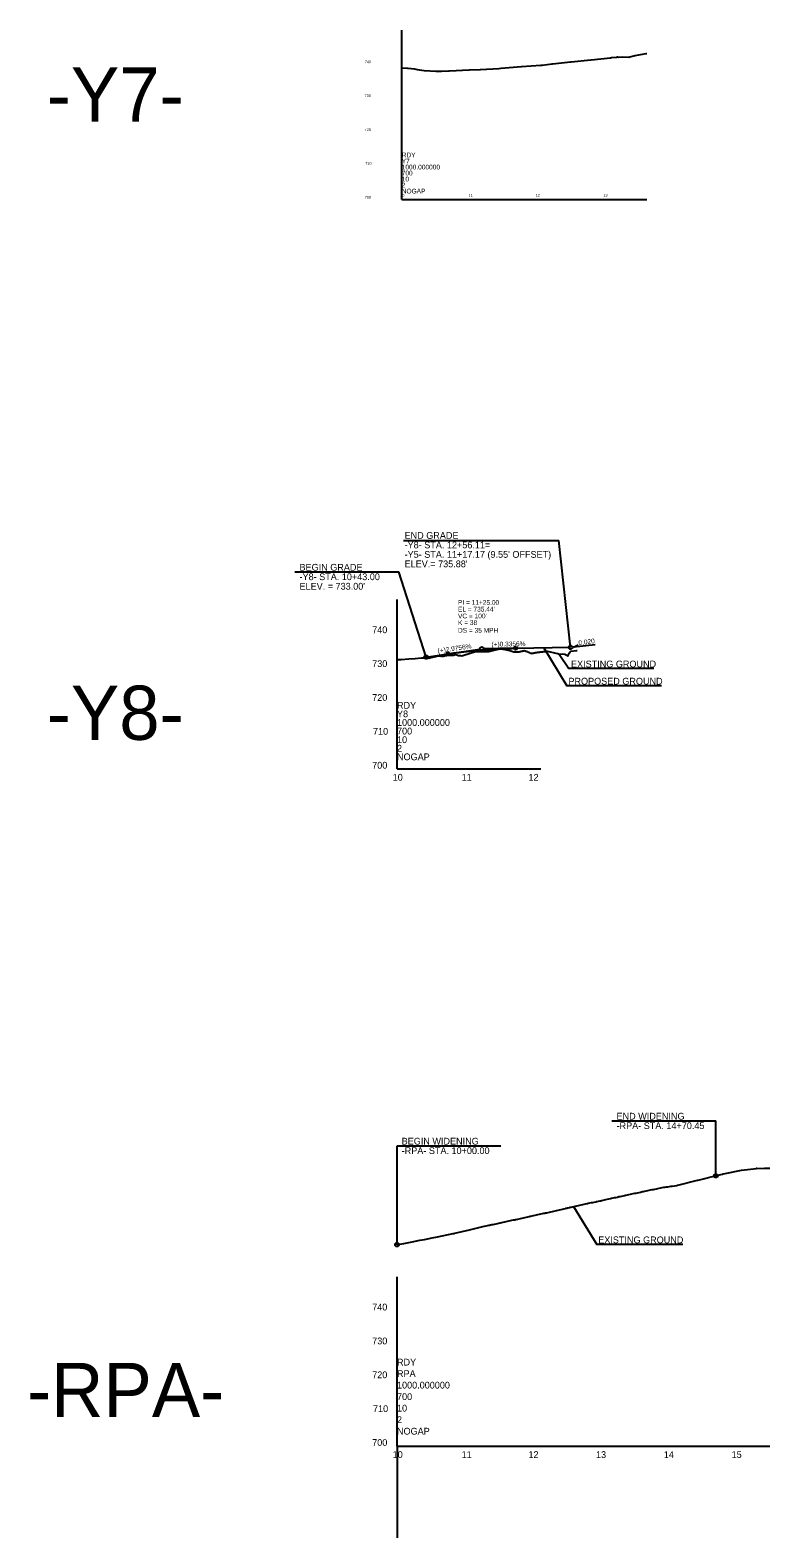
# Model space of a CAD drawing. Extents: x 1554255 to 1803987, y 659549 to 692876.
# Drawn here: x 1554255 to 1555346, y 683333 to 685559 of the extents above; entities that cross this region are included whole.
import ezdxf

# ---------------------------------------------------------------- set-up
doc = ezdxf.new("R2010")
doc.units = 0
for name, color, linetype in [('Default', 7, 'Continuous'), ('Exist Profile Cell', 7, 'Continuous'), ('Exist Vertical Profile Ground Line', 7, 'Continuous'), ('Exist Vertical Profile Horizontal Axis Label Major', 7, 'Continuous'), ('Exist Vertical Profile Vertical Axis Label', 7, 'Continuous'), ('Prop PFL Text', 7, 'Continuous'), ('Prop Vertical Profile Curve Label', 7, 'Continuous'), ('Prop Vertical Profile Grade', 7, 'Continuous'), ('Prop Vertical Profile Grade Label', 7, 'Continuous'), ('Prop VPI Label', 7, 'Continuous')]:
    doc.layers.add(name, color=color, linetype=linetype)

msp = doc.modelspace()

# ---------------------------------------------------------------- linework, layer by layer
at = {"layer": 'Exist Profile Cell'}
for p, q in [((1554802.9, 685309.3), (1554802.9, 685559.3)), ((1554802.9, 685309.3), (1555164.5, 685309.3)), ((1554802.9, 685309.3), (1554802.9, 685309.3)), ((1554795.9, 684468.6), (1554795.9, 684718.6)), ((1554795.9, 684468.6), (1555007.9, 684468.6)), ((1554795.9, 684468.6), (1554795.9, 684468.6)), ((1554795.9, 683468.6), (1554795.9, 683718.6)), ((1554795.9, 683468.6), (1555345.9, 683468.6)), ((1554795.9, 683468.6), (1554795.9, 683468.6))]:
    msp.add_line(p, q, dxfattribs=at)
at = {"layer": 'Exist Vertical Profile Ground Line'}
for points in [[(1554802.9, 685503.8), (1554811.3, 685503.2), (1554812.4, 685503.1), (1554821.5, 685502), (1554823.7, 685501.7), (1554825.5, 685501.4), (1554835.9, 685499.9), (1554853.4, 685498.8), (1554861.4, 685498.7), (1554872.6, 685499.3), (1554873.2, 685499.3), (1554902.2, 685500.7), (1554903, 685500.7), (1554918.5, 685501.4), (1554918.9, 685501.4), (1554946, 685502.8), (1554949.1, 685503), (1554949.8, 685503.1), (1554979, 685505.4), (1554979.8, 685505.4), (1555008.3, 685507.7), (1555010, 685507.8), (1555024.6, 685509.7), (1555025.3, 685509.7), (1555051.7, 685512.5), (1555052.6, 685512.6), (1555081.8, 685515.6), (1555082.2, 685515.6), (1555110.8, 685518.6), (1555112.5, 685518.8), (1555119.8, 685519.6), (1555121, 685519.7), (1555122.6, 685519.6), (1555128.3, 685519.7), (1555137.9, 685519.6), (1555139.3, 685519.9), (1555145.4, 685521.4), (1555146.9, 685521.8), (1555147.3, 685521.8), (1555163.7, 685524.8), (1555164.5, 685524.9)], [(1554795.9, 684630.1), (1554802, 684630.1), (1554813.5, 684631.1), (1554822.5, 684631.6), (1554832, 684632.5), (1554839.6, 684632.7), (1554840.3, 684632.5), (1554842.8, 684632.2), (1554844.5, 684632.5), (1554848.6, 684633.5), (1554857.8, 684635.2), (1554860.7, 684634.9), (1554861.3, 684635.3), (1554862.4, 684634.8), (1554864.6, 684634.9), (1554868.7, 684635.9), (1554870.1, 684636.2), (1554870.6, 684636.2), (1554879.1, 684636.2), (1554882.2, 684637.2), (1554882.9, 684637.2), (1554886.4, 684636.1), (1554889.4, 684636.1), (1554891.5, 684635.6), (1554905.2, 684639.7), (1554910.4, 684641.4), (1554911.1, 684641.6), (1554911.9, 684641.8), (1554912.6, 684641.8), (1554913.4, 684641.8), (1554914.1, 684641.8), (1554914.9, 684641.8), (1554915.6, 684641.8), (1554916.4, 684641.8), (1554917.1, 684641.8), (1554917.9, 684641.8), (1554918.6, 684641.8), (1554919.4, 684641.8), (1554920.1, 684641.9), (1554920.9, 684641.9), (1554921.6, 684641.9), (1554922.4, 684641.9), (1554923.1, 684641.9), (1554923.8, 684641.9), (1554924.6, 684641.9), (1554925.3, 684641.9), (1554926.1, 684641.9), (1554926.8, 684641.9), (1554927.6, 684641.8), (1554928.3, 684641.8), (1554929.1, 684641.8), (1554929.8, 684641.8), (1554930.6, 684641.8), (1554931, 684641.8), (1554931.3, 684641.9), (1554932.1, 684642.1), (1554932.8, 684642.3), (1554933.6, 684642.5), (1554934.3, 684642.7), (1554935.1, 684642.9), (1554935.8, 684643.1), (1554936.6, 684643.3), (1554937.3, 684643.5), (1554938.1, 684643.7), (1554938.8, 684643.9), (1554939.6, 684644.1), (1554940.3, 684644.3), (1554941.2, 684644.5), (1554941.8, 684644.7), (1554942.6, 684644.8), (1554943.3, 684645), (1554944, 684645.2), (1554944.8, 684645.3), (1554945.5, 684645.5), (1554946.3, 684645.7), (1554947, 684645.8), (1554947.8, 684646), (1554948.6, 684646.2), (1554949.3, 684646), (1554950, 684645.9), (1554950.8, 684645.8), (1554951.5, 684645.6), (1554952.3, 684645.5), (1554953, 684645.4), (1554953.8, 684645.2), (1554954.5, 684645.1), (1554955.3, 684644.9), (1554956, 684644.8), (1554956.8, 684644.7), (1554957.5, 684644.5), (1554958.3, 684644.4), (1554959, 684644.2), (1554959.8, 684644), (1554960.5, 684643.9), (1554960.9, 684643.8), (1554961.3, 684643.7), (1554962, 684643.5), (1554962.7, 684643.2), (1554963.5, 684643), (1554964.2, 684642.7), (1554965, 684642.5)], [(1554965, 684642.5), (1554965.7, 684642.2), (1554966.5, 684642), (1554967.2, 684641.7), (1554968, 684641.5), (1554968.7, 684641.2), (1554969.5, 684641.2), (1554970.2, 684641.2), (1554971, 684641.2), (1554971.7, 684641.2), (1554972.5, 684641.2), (1554973.2, 684641.1), (1554974, 684641.1), (1554974.3, 684641.1), (1554974.7, 684641.2), (1554975.5, 684641.4), (1554976.2, 684641.5), (1554977, 684641.7), (1554977.7, 684641.9), (1554978.5, 684642), (1554979.2, 684642.2), (1554980, 684642.4), (1554980.7, 684642.5), (1554981.5, 684642.7), (1554982.2, 684642.8), (1554982.9, 684642.9), (1554983.7, 684643.1), (1554984, 684643.1), (1554984.4, 684643), (1554985.2, 684642.7), (1554985.9, 684642.4), (1554986.7, 684642.1), (1554987.4, 684641.9), (1554988.2, 684641.6), (1554988.9, 684641.3), (1554989.7, 684641), (1554990.4, 684640.7), (1554991.2, 684640.4), (1554991.9, 684640.1), (1554992.7, 684639.7), (1554993.4, 684639.4), (1554994.3, 684639), (1554994.9, 684639.2), (1554995.7, 684639.3), (1554996.4, 684639.5), (1554997.2, 684639.6), (1554997.9, 684639.8), (1554998.7, 684639.9), (1554999.4, 684640), (1555000.2, 684640.2), (1555000.9, 684640.3), (1555001.9, 684640.5), (1555002.4, 684640.6), (1555003.1, 684640.7), (1555003.9, 684640.7), (1555004.6, 684640.8), (1555005.4, 684640.9), (1555006.1, 684641), (1555006.9, 684641.1), (1555007.6, 684641.2), (1555008.4, 684641.3), (1555009.1, 684641.3), (1555009.9, 684641.4), (1555010.6, 684641.5), (1555011.4, 684641.6), (1555012.1, 684641.7), (1555012.9, 684641.8), (1555013.6, 684641.8), (1555014.4, 684641.9), (1555015.1, 684642), (1555017.9, 684642.3), (1555030.1, 684639.5), (1555033.1, 684638.7), (1555035.1, 684638.1), (1555040.3, 684638.5), (1555043.3, 684637.9), (1555046.3, 684636.6), (1555047.7, 684634.9), (1555050.6, 684639.9), (1555051.5, 684641.1), (1555052, 684642), (1555052.5, 684642.2), (1555060.7, 684643.1), (1555061.2, 684643.2), (1555061.6, 684643.2)], [(1554795.9, 683766), (1554797.3, 683766.2), (1554800.3, 683766.8), (1554805.8, 683767.6), (1554818.3, 683770.1), (1554829.5, 683772.5), (1554836.3, 683773.6), (1554847.7, 683776.1), (1554855.6, 683777.5), (1554878.9, 683782.5), (1554879.4, 683782.6), (1554880.5, 683782.7), (1554881.1, 683782.9), (1554902.7, 683787.9), (1554924.5, 683793.1), (1554924.9, 683793.1), (1554927.2, 683793.7), (1554929.3, 683794.1), (1554931.4, 683794.6), (1554932.4, 683794.8), (1554933.6, 683795.1), (1554935.7, 683795.6), (1554937.8, 683796), (1554939.9, 683796.5), (1554942.1, 683797), (1554944.2, 683797.5), (1554946.3, 683797.9), (1554947.9, 683798.3), (1554948.5, 683798.4), (1554950.6, 683798.9), (1554952.7, 683799.3), (1554954.9, 683799.8), (1554957, 683800.2), (1554959.1, 683800.7), (1554961.3, 683801.1), (1554963.4, 683801.6), (1554965.5, 683802), (1554967.6, 683802.5), (1554969.8, 683802.9), (1554970.7, 683803.1), (1554971, 683803.2), (1554971.9, 683803.4), (1554974, 683803.9), (1554976.2, 683804.3), (1554978.3, 683804.8), (1554980.4, 683805.3), (1554982.6, 683805.7), (1554984.7, 683806.2), (1554986.8, 683806.7), (1554989, 683807.1), (1554991.1, 683807.6), (1554992.4, 683807.9), (1554992.8, 683807.9), (1554993.2, 683808), (1554995.3, 683808.5), (1554997.5, 683809), (1554999.6, 683809.5), (1555001.7, 683809.9), (1555003.9, 683810.4), (1555006, 683810.9), (1555008.1, 683811.4), (1555010.3, 683811.8), (1555012.4, 683812.3), (1555014.5, 683812.7), (1555014.9, 683812.8), (1555016.7, 683813.2), (1555018.8, 683813.7), (1555020.9, 683814.2), (1555023, 683814.7), (1555025.2, 683815.2), (1555027.3, 683815.7), (1555029.4, 683816.1), (1555031.2, 683816.5), (1555031.6, 683816.6), (1555033.7, 683817.1), (1555035.8, 683817.6), (1555038, 683818.1), (1555040.1, 683818.6), (1555042.2, 683819.1), (1555044.4, 683819.6), (1555044.9, 683819.8), (1555046.5, 683820.1), (1555047.6, 683820.4), (1555048.6, 683820.6), (1555050.7, 683821.1), (1555051.1, 683821.2), (1555052.9, 683821.6), (1555055, 683822.1), (1555057.1, 683822.6), (1555058.7, 683822.9), (1555059.3, 683823), (1555061.4, 683823.5), (1555063.5, 683824), (1555065.7, 683824.4), (1555067.8, 683824.9), (1555069.9, 683825.4), (1555072.1, 683825.8), (1555074.2, 683826.3), (1555076.3, 683826.7), (1555077.5, 683827), (1555077.8, 683827.1), (1555078.4, 683827.2), (1555080.6, 683827.7), (1555082.7, 683828.1), (1555084.8, 683828.5), (1555087, 683829), (1555089.1, 683829.4), (1555090.2, 683829.7), (1555091.2, 683829.9), (1555093.4, 683830.3), (1555095.5, 683830.7), (1555096.2, 683830.9), (1555096.5, 683830.9), (1555097.6, 683831.2), (1555099.8, 683831.7), (1555101.9, 683832.2), (1555104, 683832.7), (1555106.1, 683833.2), (1555108.3, 683833.6), (1555110.7, 683834.2), (1555112.5, 683834.6), (1555114.7, 683835), (1555116.8, 683835.5), (1555118.9, 683835.9), (1555121.1, 683836.4), (1555123.2, 683836.9), (1555125.3, 683837.3), (1555127.5, 683837.8), (1555129.6, 683838.2), (1555131.7, 683838.7), (1555133.2, 683839), (1555133.9, 683839.1), (1555136, 683839.6), (1555138.1, 683840.1), (1555140.2, 683840.5), (1555142.4, 683841), (1555144.5, 683841.4), (1555146.6, 683841.9), (1555148.8, 683842.3), (1555150.9, 683842.8), (1555153, 683843.2), (1555155.2, 683843.7), (1555158.2, 683844.3), (1555159.4, 683844.6), (1555161.6, 683845), (1555163.7, 683845.5), (1555165.8, 683846), (1555167.9, 683846.4), (1555170.1, 683846.9), (1555172.2, 683847.3), (1555174.3, 683847.7), (1555176.5, 683848.2), (1555178.6, 683848.6), (1555180.7, 683849.1), (1555182.9, 683849.5), (1555185, 683849.9), (1555187.1, 683850.3), (1555189.3, 683850.7), (1555191.4, 683851), (1555193.5, 683851.3), (1555195.6, 683851.6), (1555197.8, 683852), (1555199.9, 683852.3), (1555202, 683852.6), (1555208.7, 683853.6), (1555209.4, 683853.7), (1555210.4, 683854), (1555239.3, 683861.1), (1555240.2, 683861.4), (1555269.4, 683868.6), (1555276.2, 683870.2), (1555276.9, 683870.4), (1555277.5, 683870.5), (1555304.3, 683876.2), (1555312.9, 683877.2), (1555326.2, 683878.3), (1555326.2, 683878.8), (1555326.3, 683878.3), (1555338.1, 683878.8), (1555340.7, 683879), (1555343, 683879), (1555345.9, 683879)]]:
    msp.add_lwpolyline(points, dxfattribs=at)
at = {"layer": 'Prop PFL Text'}
for p, q in [((1554805.7, 684805.9), (1555034.4, 684805.9)), ((1555052, 684648), (1555034.4, 684805.9)), ((1554645.2, 684759.5), (1554798.6, 684759.5)), ((1554838.9, 684633.6), (1554798.6, 684759.5)), ((1555012.5, 684647.3), (1555046.4, 684591)), ((1555035.1, 684638.1), (1555049.4, 684616.5)), ((1555174.7, 684616.5), (1555049.4, 684616.5)), ((1555185.9, 684591), (1555046.4, 684591)), ((1555113, 683948.9), (1555266.4, 683948.9)), ((1555266.4, 683867.8), (1555266.4, 683948.9)), ((1554795.9, 683912.1), (1554949.3, 683912.1)), ((1554795.9, 683766), (1554795.9, 683912.1)), ((1555056.5, 683822.4), (1555090.5, 683766.1)), ((1555217.5, 683766.1), (1555090.5, 683766.1)), ((1554795.9, 683468.6), (1554795.9, 683333.1))]:
    msp.add_line(p, q, dxfattribs=at)
at = {"layer": 'Prop Vertical Profile Curve Label'}
for centre in [(1554870.9, 684638.4), (1554970.9, 684646.6)]:
    msp.add_circle(centre, 2.25, dxfattribs=at)
at = {"layer": 'Prop Vertical Profile Grade'}
for p, q in [((1554970.9, 684646.6), (1555052, 684648)), ((1554838.9, 684633.6), (1554870.9, 684638.4))]:
    msp.add_line(p, q, dxfattribs=at)
msp.add_spline([(1554870.9, 684638.4), (1554872.9, 684638.7), (1554874.9, 684639), (1554876.9, 684639.2), (1554878.9, 684639.5), (1554880.9, 684639.8), (1554882.9, 684640.1), (1554884.9, 684640.3), (1554886.9, 684640.6), (1554888.9, 684640.8), (1554890.9, 684641.1), (1554892.9, 684641.3), (1554894.9, 684641.6), (1554896.9, 684641.8), (1554898.9, 684642), (1554900.9, 684642.2), (1554902.9, 684642.5), (1554904.9, 684642.7), (1554906.9, 684642.9), (1554908.9, 684643.1), (1554910.9, 684643.3), (1554912.9, 684643.5), (1554914.9, 684643.6), (1554916.9, 684643.8), (1554918.9, 684644), (1554920.9, 684644.2), (1554922.9, 684644.3), (1554924.9, 684644.5), (1554926.9, 684644.6), (1554928.9, 684644.8), (1554930.9, 684644.9), (1554932.9, 684645.1), (1554934.9, 684645.2), (1554936.9, 684645.3), (1554938.9, 684645.4), (1554940.9, 684645.5), (1554942.9, 684645.7), (1554944.9, 684645.8), (1554946.9, 684645.9), (1554948.9, 684646), (1554950.9, 684646), (1554952.9, 684646.1), (1554954.9, 684646.2), (1554956.9, 684646.3), (1554958.9, 684646.3), (1554960.9, 684646.4), (1554962.9, 684646.5), (1554964.9, 684646.5), (1554966.9, 684646.6), (1554968.9, 684646.6), (1554970.9, 684646.6)], degree=3, dxfattribs=at)
at = {"layer": 'Prop VPI Label'}
for p, q in [((1554870.9, 684638.4), (1554918.2, 684645.4)), ((1554970.9, 684646.6), (1554923.7, 684645.9)), ((1555088, 684651.9), (1555056.2, 684648.1)), ((1555056.2, 684648.1), (1555063, 684651.6))]:
    msp.add_line(p, q, dxfattribs=at)
for centre in [(1554920.9, 684645.8), (1555052, 684648), (1554838.9, 684633.6), (1555266.4, 683867.8), (1554795.9, 683766)]:
    msp.add_circle(centre, 2.75, dxfattribs=at)

# ---------------------------------------------------------------- texts
at = {"layer": 'Default'}
for s, p in [('740', (1554748.3, 685510.5)), ('730', (1554748.1, 685460.5)), ('720', (1554748.1, 685410.5)), ('710', (1554749.1, 685360.5)), ('700', (1554748.3, 685310.5)), ('10', (1554800.6, 685313.5)), ('11', (1554901.5, 685313.5)), ('12', (1555000.5, 685313.5)), ('13', (1555100.5, 685313.5))]:
    msp.add_text(s, height=4, dxfattribs=at).set_placement(p)
at = {"layer": 'Exist Profile Cell'}
for s, height, p in [('RDY', 7, (1554802.9, 685371.4)), ('Y7', 7, (1554802.9, 685362.5)), ('1000.000000', 7, (1554802.9, 685353.6)), ('700', 7, (1554802.9, 685344.8)), ('2', 7, (1554802.9, 685327)), ('10', 7, (1554802.9, 685335.9)), ('NOGAP', 7, (1554802.9, 685318.1)), ('Y8', 10, (1554795.9, 684544.7)), ('RDY', 10, (1554795.9, 684557.3)), ('700', 10, (1554795.9, 684519.3)), ('1000.000000', 10, (1554795.9, 684532)), ('10', 10, (1554795.9, 684506.6)), ('2', 10, (1554795.9, 684494)), ('NOGAP', 10, (1554795.9, 684481.3)), ('RDY', 10, (1554795.9, 683587.6)), ('RPA', 10, (1554795.9, 683570.6)), ('1000.000000', 10, (1554795.9, 683553.6)), ('700', 10, (1554795.9, 683536.6)), ('10', 10, (1554795.9, 683519.6)), ('2', 10, (1554795.9, 683502.6)), ('NOGAP', 10, (1554795.9, 683485.6))]:
    msp.add_text(s, height=height, dxfattribs=at).set_placement(p)
at = {"layer": 'Exist Vertical Profile Horizontal Axis Label Major'}
for s, p in [('10', (1554789.5, 684451.1)), ('11', (1554891.3, 684451.1)), ('12', (1554989.9, 684451.1)), ('10', (1554789.5, 683451.1)), ('11', (1554891.3, 683451.1)), ('12', (1554989.9, 683451.1)), ('13', (1555089.5, 683451.1)), ('14', (1555189.6, 683451.1)), ('15', (1555289.5, 683451.1))]:
    msp.add_text(s, height=10, dxfattribs=at).set_placement(p)
at = {"layer": 'Exist Vertical Profile Vertical Axis Label'}
for s, height, p in [('-Y7-', 80, (1554279.2, 685424.3)), ('740', 10, (1554759.3, 684668.9)), ('730', 10, (1554759.3, 684618.9)), ('-Y8-', 80, (1554279.2, 684511.4)), ('720', 10, (1554759.3, 684568.9)), ('710', 10, (1554760.5, 684518.9)), ('700', 10, (1554759.3, 684468.9)), ('740', 10, (1554759.3, 683668.9)), ('730', 10, (1554759.3, 683618.9)), ('-RPA-', 80, (1554250, 683511.4)), ('720', 10, (1554759.3, 683568.9)), ('710', 10, (1554760.5, 683518.9)), ('700', 10, (1554759.3, 683468.9))]:
    msp.add_text(s, height=height, dxfattribs=at).set_placement(p)
at = {"layer": 'Prop PFL Text'}
for s, p in [('-Y8- STA. 12+56.11=', (1554807.1, 684794.2)), ('END GRADE', (1554807.1, 684808.2)), ("-Y5- STA. 11+17.17 (9.55' OFFSET)", (1554807.1, 684780.2)), ("ELEV.= 735.88'", (1554807.1, 684766.2)), ('-Y8- STA. 10+43.00', (1554652.1, 684747.2)), ('BEGIN GRADE', (1554652.1, 684761.2)), ("ELEV. = 733.00'", (1554652.1, 684733.2)), ('END WIDENING', (1555119.8, 683950.7)), ('-RPA- STA. 14+70.45', (1555119.8, 683936.7)), ('-RPA- STA. 10+00.00', (1554802.8, 683899.8)), ('BEGIN WIDENING', (1554802.8, 683913.8))]:
    msp.add_text(s, height=10, dxfattribs=at).set_placement(p)
for s, p in [('EXISTING GROUND', (1555052.6, 684618.4)), ('PROPOSED GROUND', (1555048.8, 684593)), ('EXISTING GROUND', (1555092.8, 683768.1))]:
    msp.add_text(s, height=10, rotation=360, dxfattribs=at).set_placement(p)
at = {"layer": 'Prop Vertical Profile Curve Label'}
for s, p in [("VC = 100'", (1554885.9, 684690.8)), ('K = 38', (1554885.9, 684680.9)), ('DS = 35 MPH', (1554885.9, 684669.6))]:
    msp.add_text(s, height=7, dxfattribs=at).set_placement(p)
at = {"layer": 'Prop Vertical Profile Grade Label'}
for s, rotation, p in [('(+)2.9756%', 8.4624, (1554856.4, 684639.2)), ('(+)0.3356%', 0.9613, (1554935.3, 684649)), ('0.020', 7.0007, (1555064, 684651.2))]:
    msp.add_text(s, height=7, rotation=rotation, dxfattribs=at).set_placement(p)
at = {"layer": 'Prop VPI Label'}
for s, p in [('PI = 11+25.00', (1554885.9, 684710.8)), ("EL = 735.44'", (1554885.9, 684700.8))]:
    msp.add_text(s, height=7, dxfattribs=at).set_placement(p)

doc.saveas('drawing.dxf')
